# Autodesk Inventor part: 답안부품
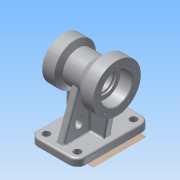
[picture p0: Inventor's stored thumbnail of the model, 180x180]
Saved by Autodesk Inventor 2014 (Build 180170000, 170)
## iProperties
Created: 2015-08
Part Number: 답안부품
Material: 알루미늄 6061
Document SubType Name: Modeling
Designer: sda20
Density: 2.71 g/cm^3
Appearance: 알루미늄 - 평지
Mass: 1068.93 g
Surface Area: 780.721 cm^2
Volume: 394.44 cm^3
Author: sda20
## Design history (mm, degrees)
sketch "스케치9"
  geometry: C1 r 26 at (0, 0); 1 further point
  constraints: 1 centre point, 1 coincident
  dimensions: "d93" = 52 diameter of C1
extrude "돌출4" new body sketch "스케치9" stored distance "d94" = 50; taper "d95" = 0 deg
sketch "스케치10"
  geometry: C1 r 26 at (0, 0) reference; C2 r 35 at (0, 0)
  constraints: 1 centre point, 1 coincident
  dimensions: "d96" = 70 diameter of C2
extrude "돌출5" join sketch "스케치10" distance "d97" = 20; taper "d98" = 0 deg
sketch "스케치11"
  geometry: C1 r 26 at (0, 0) reference; C2 r 40 at (0, 0)
  constraints: 1 centre point, 1 coincident
  dimensions: "d99" = 80 diameter of C2
extrude "돌출6" join sketch "스케치11" distance "d100" = 20; taper "d101" = 0 deg
sketch "스케치12"
  geometry: L1 (-35, 25)-(35, 25) reference; L2 (35, 45)-(-35, 45) reference; L3 (0, 45)-(0, -45); L4 (-40, -45)-(40, -45) reference; L5 (35, 25)-(26, 19.804); L6 (26, -25)-(26, 25) reference; L7 (40, -25)-(-40, -25) reference; L8 (40, -25)-(26, -8.315); 1 further point
  constraints: 7 end point, 2 midpoint, 2 point on line, 1 perpendicular
  dimensions: "d102" = 60 deg angle of L6 L5; "d103" = 40 deg angle of L6 L8
revolve "회전3" sketch "스케치12" stored, may be unused: angle "d104" = 90 deg
node "작업 평면4"
sketch "스케치13"
  geometry: L1 (61, 40)-(-61, 40); L2 (-61, 40)-(-61, -40); L3 (-61, -40)-(61, -40); L4 (61, -40)-(61, 40); L5 (61, 40)-(-61, -40); L6 (-61, 40)-(61, -40); 1 further point
  constraints: 12 end point, 2 midpoint, 2 parallel, 1 horizontal, 1 perpendicular
  dimensions: "d106" = 122 distance of L3.end L2.end; "d107" = 80 distance of L3.end L1.start
extrude "돌출7" join sketch "스케치13" distance "d108" = 12; taper "d109" = 0 deg
hole "구멍9" diameter "d122" = 52; stored, may be unused: countersink angle "d126" = 90 deg, drill point angle "d128" = 0 deg; dims "d120" = 10, "d121" = 10, "d123" = 6, "d124" = 4, "d125" = 2, "d127" = 20
hole "구멍10" diameter "d131" = 38; stored, may be unused: countersink angle "d135" = 90 deg, drill point angle "d137" = 0 deg; dims "d129" = 10, "d130" = 10, "d132" = 6, "d133" = 4, "d134" = 2, "d136" = 3
hole "구멍11" diameter "d140" = 40; stored, may be unused: countersink angle "d144" = 90 deg, drill point angle "d146" = 0 deg; dims "d138" = 10, "d139" = 10, "d141" = 6, "d142" = 4, "d143" = 2, "d145" = 17
hole "구멍12" diameter "d149" = 32; stored, may be unused: countersink angle "d153" = 90 deg, drill point angle "d155" = 0 deg; dims "d147" = 10, "d148" = 10, "d150" = 6, "d151" = 4, "d152" = 2, "d154" = 17
sketch "스케치18" dims "d156" = 54
  geometry: C1 r 20 at (0, 0) reference; C2 r 35 at (0, 0) reference; 2 further points
  constraints: 2 vertical alignment, 1 coincident, 2 other
hole "구멍13" sketch "스케치18" at (0, 27) diameter "d157" = 3.242; stored, may be unused: countersink angle "d161" = 90 deg, drill point angle "d163" = 118 deg; dims "d158" = 10, "d159" = 4, "d160" = 2, "d162" = 13
sketch "스케치19" dims "d167" = 66
  geometry: C1 r 26 at (0, 0) reference; C2 r 40 at (0, 0) reference; 2 further points
  constraints: 2 vertical alignment, 1 coincident, 2 other
hole "구멍14" sketch "스케치19" at (0, 33) diameter "d168" = 3.242; stored, may be unused: countersink angle "d172" = 90 deg, drill point angle "d174" = 118 deg; dims "d169" = 10, "d170" = 4, "d171" = 2, "d173" = 13
sketch "스케치23"
  geometry: L1 (25.091, -6.815)-(51, -78); L2 (-61, -78)-(61, -78) reference; L3 (61, -90)-(61, -78) reference; L4 (61, -78)-(-61, -78) reference; L5 (0, -78)-(0, -26); L6 (0, -78)-(51, -78); A1 r 26 centre (0, 0) between (0, -26) and (25.091, -6.815); 1 further point
  constraints: 6 end point, 2 point on circle, 1 centre point, 1 coincident, 1 collinear, 1 midpoint, 1 perpendicular, 1 point on line
  dimensions: "d185" = 10 distance from line of L3 L1.end; "d186" = 70 deg angle of L2 L1; "d192" = 26 radius of A1
extrude "돌출9" join sketch "스케치23" stored distance "d193" = 12; taper "d194" = 0 deg
sketch "스케치24"
  geometry: L1 (-35, 25)-(-35, 45) reference; L2 (-35, 25)-(-26, 19.804) reference; L3 (-26, -8.315)-(-26, 19.804) reference; L4 (-26, -8.315)-(-40, -25) reference; L5 (-40, -25)-(-40, -45) reference; L6 (-78, -40)-(-78, 40) reference; L7 (-40, -36.7)-(-78, -30); L8 (-90, -40)-(-78, -40) reference; L9 (-35, 35)-(-78, 35); 1 further point
  constraints: 4 end point, 3 point on line, 1 midpoint, 1 perpendicular
  dimensions: "d195" = 10 distance from line of L8 L7.end; "d196" = 80 deg angle of L6 L7
extrude "돌출10" join sketch "스케치24" stored distance "d197" = 12; taper "d198" = 0 deg
sketch "스케치25"
  geometry: 2 further points
  dimensions: "d199" = 47 horizontal distance of point (0, 0) point (-47, 26); "d200" = 26 vertical distance of point (0, 0) point (-47, 26)
hole "구멍15" sketch "스케치25" at (-47, 26) diameter "d201" = 12; stored, may be unused: countersink angle "d205" = 90 deg, drill point angle "d207" = 0 deg; dims "d202" = 12, "d203" = 4, "d204" = 2, "d206" = 13
sketch "스케치26"
  geometry: L1 (-6, -78)-(-51, -78) reference; L2 (-18, -54)-(-18, -60); L3 (-30, -54)-(-30, -60); A1 r 26 centre (0, 0) between (-25.091, -6.815) and (0, -26) reference; A2 r 6 centre (-24, -60) between (-30, -60) and (-18, -60); A3 r 6 centre (-24, -54) between (-18, -54) and (-30, -54); 2 further points
  constraints: 6 point on circle, 4 end point, 3 tangent, 3 vertical alignment, 2 centre point, 1 parallel
  dimensions: "d210" = 12 diameter of A2; "d211" = 18 distance from line of L1 A2.centre; "d212" = 24 horizontal distance of A1.centre A2.centre; "d213" = 12 diameter of A3; "d214" = 18 distance of point (-24, -48) point (-24, -66)
extrude "돌출11" cut sketch "스케치26" stored distance "d215" = 0; taper "d216" = 0 deg
fillet "모깎기1" dims "d217" = 0.3
fillet "모깎기2" dims "d218" = 5
fillet "모깎기3" dims "d219" = 0.3
fillet "모깎기4" dims "d220" = 14
fillet "모깎기5" dims "d221" = 3
sketch "스케치28"
  geometry: L1 (-40, -78)-(-26, -78) reference; L2 (-40, -78)-(-40, -90) reference; L3 (-35, -35)-(-35, -75) reference; 2 further points
  constraints: 1 other
  dimensions: "d222" = 24 distance from line of L1 point (-19, -54); "d224" = 16 distance from line of L3 point (-19, -54)
feature "엠보싱1" sketch "스케치28" dims "d225" = 0.5, "d226" = 0
chamfer "모따기1" distance "d227" = 1; stored, may be unused: second distance "d228" = 2, angle "d229" = 45 deg
fillet "모깎기6" dims "d230" = 3
fillet "모깎기7" dims "d231" = 3
node "솔리드2"
pattern_circular "원형 패턴1" dims angle "d165" = 360 deg
pattern_circular "원형 패턴2" dims angle "d176" = 360 deg
mirror "대칭2"
mirror "대칭3"
mirror "대칭4"
mirror "대칭5"
